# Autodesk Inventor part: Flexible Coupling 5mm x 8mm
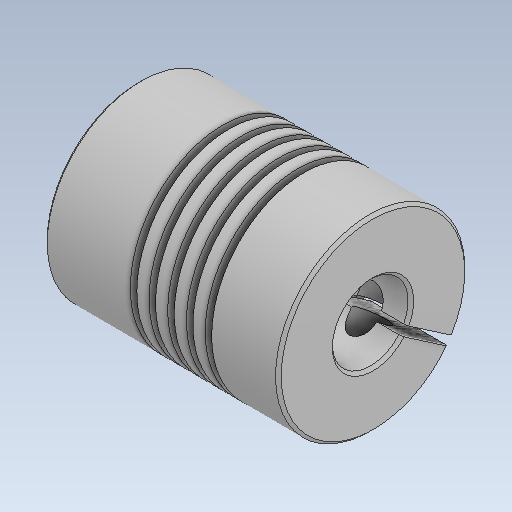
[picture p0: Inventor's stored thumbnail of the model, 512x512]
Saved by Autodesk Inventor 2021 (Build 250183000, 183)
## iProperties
Created: 2026-10
Part Number: Flexible Coupling 5mm x 8mm
Material: Steel
Document SubType Name: Modeling
Designer: hp
Density: 7.85 g/cm^3
Appearance: Default
Author: hp
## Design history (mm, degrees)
feature "Body1"
body "Solid1"
